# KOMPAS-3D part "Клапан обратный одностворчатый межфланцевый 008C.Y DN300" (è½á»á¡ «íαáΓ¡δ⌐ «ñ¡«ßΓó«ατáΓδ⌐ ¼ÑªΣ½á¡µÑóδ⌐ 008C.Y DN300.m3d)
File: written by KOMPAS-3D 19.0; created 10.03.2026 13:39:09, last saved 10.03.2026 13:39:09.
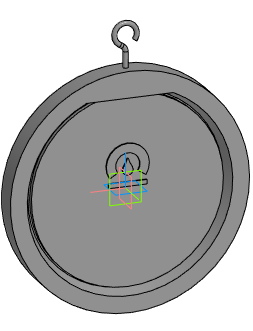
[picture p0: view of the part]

Document properties: Автор: Евгений; Полное имя файла: E:\Dendor\3D для проектировщиков\5.1 Тип 008C. Клапан обратный одностворчатый межфланцевый\stp_Клапан обратный одностворчатый межфланцевый 008C.Y\Клапан обратный одностворчатый межфланцевый 008C.Y DN300.m3d

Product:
- Part/product: Клапан обратный одностворчатый межфланцевый 008C.Y DN300

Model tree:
1. Операция без истории:1  (labels: Клапан обратный одностворчатый межфланцевый 008C.Y DN300)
